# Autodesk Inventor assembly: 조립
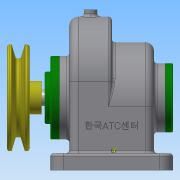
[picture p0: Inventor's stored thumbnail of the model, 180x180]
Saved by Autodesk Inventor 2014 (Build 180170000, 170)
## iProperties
Created: 2017-11
Part Number: 조립
Document SubType Name: Assembly
Designer: net
Author: net
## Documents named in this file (14)
- C:\Users\net\Desktop\471107V1003\조립.iam
- C:\Users\net\Desktop\471107V1003\본체.ipt
- C:\Users\net\Desktop\471107V1003\뒤커버.ipt
- C:\Users\net\Desktop\471107V1003\베어링 6002.ipt
- C:\Users\net\Desktop\471107V1003\앞커버.ipt
- C:\Users\net\Desktop\471107V1003\축.ipt
- C:\Users\net\Desktop\471107V1003\볼트 M3 x 8.ipt
- C:\Users\net\Desktop\471107V1003\스퍼기어.ipt
- C:\Users\net\Desktop\471107V1003\키 - 6 x 6 x 22.ipt
- C:\Users\net\Desktop\471107V1003\키 - 5 x 5 x 18.ipt
- C:\Users\net\Desktop\471107V1003\멈춤나사 - M4 x 10.ipt
- 멈춤나사 - M4 x 10.ipt
- C:\Users\net\Desktop\471107V1003\V-벨트풀리.ipt
- C:\Users\net\Desktop\471107V1003\오일 실 15 30 7.ipt
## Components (1 placed, 1 different names)
1. V-벨트풀리:1
